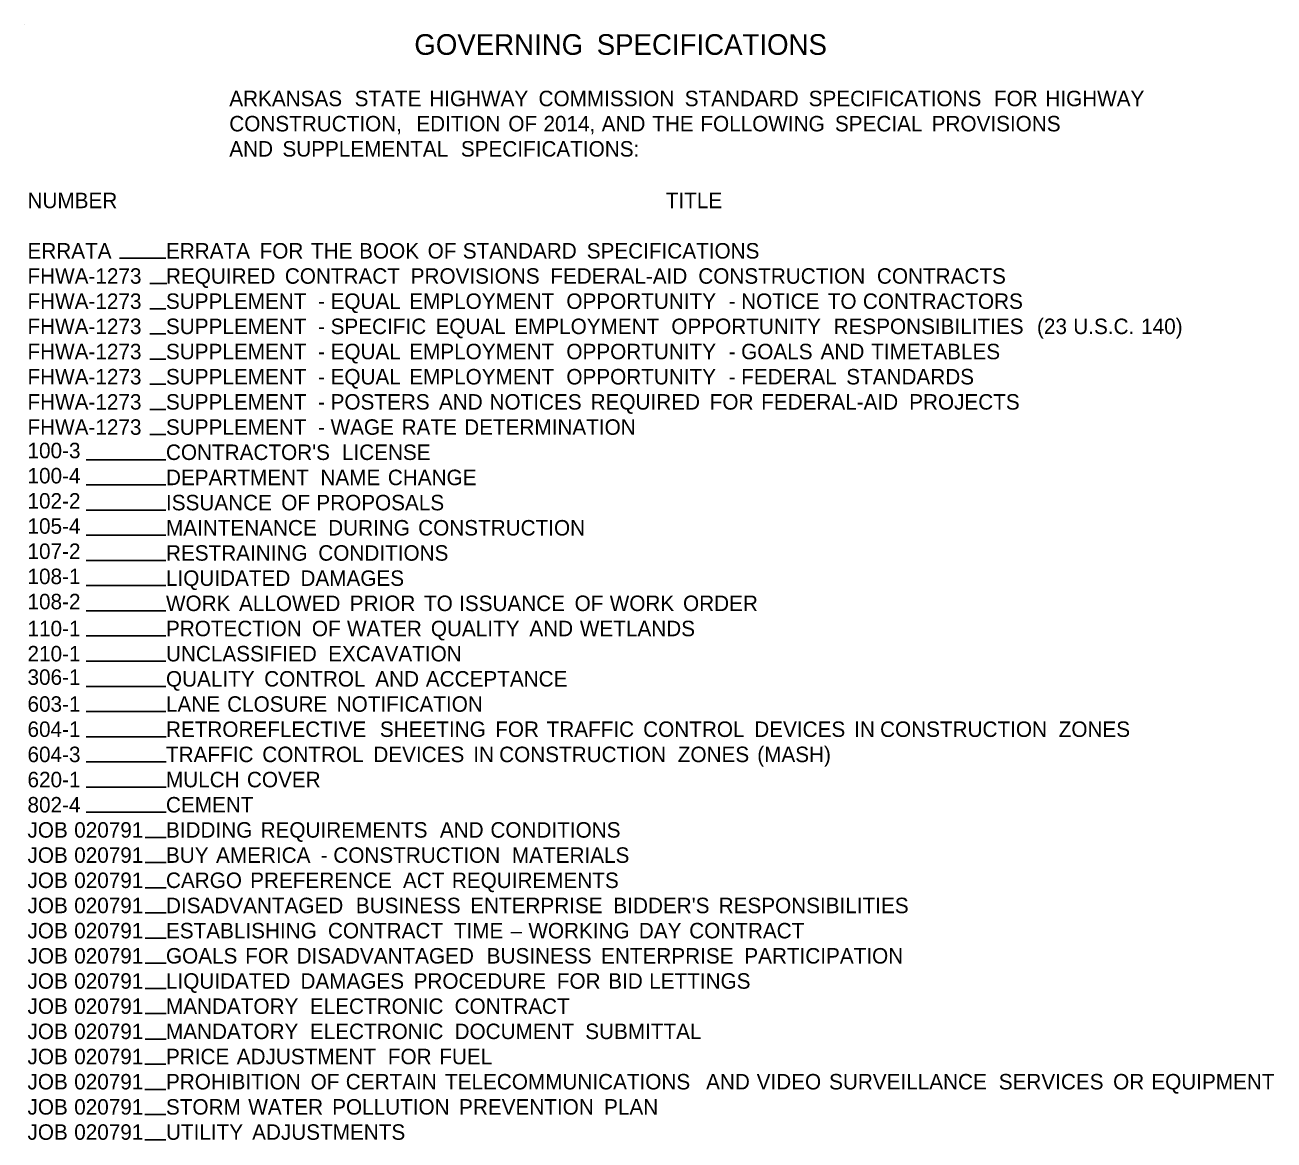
# Model space of a CAD drawing. Extents: x -1218 to 1646, y -1033 to 999.
# Drawn here: x -1218 to -250, y -181 to 682 of the extents above; entities that cross this region are included whole.
import ezdxf

# ---------------------------------------------------------------- set-up
doc = ezdxf.new("R2010")
doc.units = 0
doc.layers.add('Default', color=7, linetype='Continuous')

msp = doc.modelspace()

# ---------------------------------------------------------------- linework, layer by layer
at = {"layer": 'Default'}
for p, q in [((-1217.63, 682.26), (-1217.63, 682.26)), ((-1144.37, 501.55), (-1108.54, 501.55)), ((-1120.87, 482.05), (-1107.74, 482.05)), ((-1120.87, 462.55), (-1108.54, 462.55)), ((-1120.87, 443.05), (-1108.54, 443.05)), ((-1120.87, 423.55), (-1108.54, 423.55)), ((-1120.87, 404.05), (-1108.54, 404.05)), ((-1120.87, 384.55), (-1108.54, 384.55)), ((-1120.87, 365.05), (-1108.54, 365.05)), ((-1170.14, 345.55), (-1108.61, 345.55)), ((-1170.14, 326.05), (-1108.61, 326.05)), ((-1170.14, 306.55), (-1108.61, 306.55)), ((-1170.14, 287.05), (-1108.61, 287.05)), ((-1170.14, 267.55), (-1108.61, 267.55)), ((-1170.14, 248.05), (-1108.61, 248.05)), ((-1170.14, 228.55), (-1108.61, 228.55)), ((-1170.14, 209.05), (-1108.61, 209.05)), ((-1170.14, 189.55), (-1108.61, 189.55)), ((-1170.14, 170.05), (-1108.61, 170.05)), ((-1170.14, 150.55), (-1108.61, 150.55)), ((-1170.14, 131.05), (-1108.24, 131.05)), ((-1170.14, 111.55), (-1108.24, 111.55)), ((-1170.14, 92.05), (-1108.24, 92.05)), ((-1170.14, 72.55), (-1108.24, 72.55)), ((-1124.67, 53.05), (-1108.24, 53.05)), ((-1124.67, 33.55), (-1108.24, 33.55)), ((-1124.67, 14.05), (-1108.24, 14.05)), ((-1124.67, -5.45), (-1108.24, -5.45)), ((-1124.67, -24.95), (-1108.24, -24.95)), ((-1124.67, -44.45), (-1108.24, -44.45)), ((-1124.67, -63.95), (-1108.24, -63.95)), ((-1124.67, -83.45), (-1108.24, -83.45)), ((-1124.67, -103.14), (-1108.24, -103.14)), ((-1124.86, -122.64), (-1108.43, -122.64)), ((-1124.86, -142.14), (-1108.43, -142.14)), ((-1124.86, -161.51), (-1108.43, -161.51)), ((-1124.86, -181.27), (-1108.43, -181.27))]:
    msp.add_line(p, q, dxfattribs=at)

# ---------------------------------------------------------------- texts
for s, height, p in [('GOVERNING', 16, (-916.06, 659.14)), (' SPECIFICATIONS', 16, (-780.76, 659.14)), ('           ARKANSAS', 12, (-1108.43, 619.34)), (' STATE', 12, (-966.76, 619.34)), (' HIGHWAY', 12, (-908.96, 619.34)), (' COMMISSION', 12, (-824.32, 619.34)), (' STANDARD', 12, (-711.11, 619.34)), (' SPECIFICATIONS', 12, (-615.11, 619.34)), (' FOR', 12, (-471.58, 619.34)), (' HIGHWAY', 12, (-431.76, 619.34)), ('           CONSTRUCTION,', 12, (-1108.43, 599.84)), (' EDITION', 12, (-918.98, 599.84)), (' OF', 12, (-847.7, 599.84)), (' 2014,', 12, (-820.52, 599.84)), (' AND', 12, (-775.42, 599.84)), (' THE', 12, (-736.26, 599.84)), (' FOLLOWING', 12, (-698.96, 599.84)), (' SPECIAL', 12, (-594.75, 599.84)), (' PROVISIONS', 12, (-519.86, 599.84)), ('           AND', 12, (-1108.43, 580.34)), (' SUPPLEMENTAL', 12, (-1022.71, 580.34)), (' SPECIFICATIONS:', 12, (-884.47, 580.34)), ('NUMBER', 12, (-1215.68, 540.36)), ('TITLE', 12, (-721.31, 540.36)), ('ERRATA', 12, (-1215.68, 501.36)), ('ERRATA', 12, (-1108.43, 501.36)), (' FOR', 12, (-1040.38, 501.36)), (' THE', 12, (-1000.56, 501.36)), (' BOOK', 12, (-963.26, 501.36)), (' OF', 12, (-910.18, 501.36)), (' STANDARD', 12, (-883.01, 501.36)), (' SPECIFICATIONS', 12, (-787.01, 501.36)), ('FHWA-1273', 12, (-1215.68, 481.86)), ('REQUIRED', 12, (-1108.43, 481.86)), (' CONTRACT', 12, (-1020.82, 481.86)), (' PROVISIONS', 12, (-923.35, 481.86)), (' FEDERAL-AID', 12, (-815.21, 481.86)), (' CONSTRUCTION', 12, (-700.58, 481.86)), (' CONTRACTS', 12, (-562.22, 481.86)), ('FHWA-1273', 12, (-1215.68, 462.36)), ('SUPPLEMENT', 12, (-1108.43, 462.36)), (' EQUAL', 12, (-985.38, 462.36)), (' EMPLOYMENT', 12, (-924.47, 462.36)), (' OPPORTUNITY', 12, (-802.76, 462.36)), (' NOTICE', 12, (-667.4, 462.36)), (' TO', 12, (-600.3, 462.36)), (' CONTRACTORS', 12, (-573.11, 462.36)), (' -', 12, (-995.09, 462.36)), (' -', 12, (-677.12, 462.36)), ('FHWA-1273', 12, (-1215.68, 442.86)), ('SUPPLEMENT', 12, (-1108.43, 442.86)), (' SPECIFIC', 12, (-985.38, 442.86)), (' EQUAL', 12, (-904.06, 442.86)), (' EMPLOYMENT', 12, (-843.15, 442.86)), (' OPPORTUNITY', 12, (-721.44, 442.86)), (' RESPONSIBILITIES', 12, (-595.8, 442.86)), (' (23', 12, (-438.27, 442.86)), (' U.S.C.', 12, (-410.15, 442.86)), (' 140)', 12, (-357.59, 442.86)), (' -', 12, (-995.09, 442.86)), ('FHWA-1273', 12, (-1215.68, 423.36)), ('SUPPLEMENT', 12, (-1108.43, 423.36)), (' EQUAL', 12, (-985.38, 423.36)), (' EMPLOYMENT', 12, (-924.47, 423.36)), (' OPPORTUNITY', 12, (-802.76, 423.36)), (' GOALS', 12, (-667.4, 423.36)), (' AND', 12, (-605.85, 423.36)), (' TIMETABLES', 12, (-566.68, 423.36)), (' -', 12, (-995.09, 423.36)), (' -', 12, (-677.12, 423.36)), ('FHWA-1273', 12, (-1215.68, 403.86)), ('SUPPLEMENT', 12, (-1108.43, 403.86)), (' EQUAL', 12, (-985.38, 403.86)), (' EMPLOYMENT', 12, (-924.47, 403.86)), (' OPPORTUNITY', 12, (-802.76, 403.86)), (' STANDARDS', 12, (-586, 403.86)), (' -', 12, (-995.09, 403.86)), (' -', 12, (-677.12, 403.86)), (' FEDERAL', 12, (-667.4, 403.86)), ('FHWA-1273', 12, (-1215.68, 384.36)), ('SUPPLEMENT', 12, (-1108.43, 384.36)), (' -', 12, (-995.09, 384.36)), (' POSTERS', 12, (-985.38, 384.36)), (' AND', 12, (-901.46, 384.36)), (' NOTICES', 12, (-862.29, 384.36)), (' REQUIRED', 12, (-783.98, 384.36)), (' FOR', 12, (-691.72, 384.36)), (' FEDERAL-AID', 12, (-651.89, 384.36)), (' PROJECTS', 12, (-537.26, 384.36)), ('FHWA-1273', 12, (-1215.68, 364.86)), ('SUPPLEMENT', 12, (-1108.43, 364.86)), (' -', 12, (-995.09, 364.86)), (' WAGE', 12, (-985.38, 364.86)), (' RATE', 12, (-930.38, 364.86)), (' DETERMINATION', 12, (-881.9, 364.86)), ('100-3', 12, (-1215.68, 346.71)), ("CONTRACTOR'S", 12, (-1108.43, 345.36)), (' LICENSE', 12, (-976.61, 345.36)), ('100-4', 12, (-1215.68, 327.21)), ('DEPARTMENT', 12, (-1108.43, 325.86)), (' NAME', 12, (-993.24, 325.86)), (' CHANGE', 12, (-941.04, 325.86)), ('102-2', 12, (-1215.68, 307.71)), ('ISSUANCE', 12, (-1108.43, 306.36)), (' OF', 12, (-1023.6, 306.36)), (' PROPOSALS', 12, (-996.43, 306.36)), ('105-4', 12, (-1215.68, 288.21)), ('MAINTENANCE', 12, (-1108.43, 286.86)), (' DURING', 12, (-987.28, 286.86)), (' CONSTRUCTION', 12, (-917.54, 286.86)), ('107-2', 12, (-1215.68, 268.71)), ('RESTRAINING', 12, (-1108.43, 267.36)), (' CONDITIONS', 12, (-994.89, 267.36)), ('108-1', 12, (-1215.68, 249.21)), ('LIQUIDATED', 12, (-1108.43, 247.86)), (' DAMAGES', 12, (-1008.71, 247.86)), ('108-2', 12, (-1215.68, 229.71)), ('WORK', 12, (-1108.43, 228.36)), (' ALLOWED', 12, (-1056.31, 228.36)), (' PRIOR', 12, (-970.56, 228.36)), (' TO', 12, (-913.03, 228.36)), (' ISSUANCE', 12, (-885.84, 228.36)), (' OF', 12, (-796.35, 228.36)), (' WORK', 12, (-769.18, 228.36)), (' ORDER', 12, (-712.4, 228.36)), ('110-1', 12, (-1215.68, 208.86)), ('PROTECTION', 12, (-1108.43, 208.86)), (' OF', 12, (-999.87, 208.86)), (' WATER', 12, (-972.7, 208.86)), (' QUALITY', 12, (-907.72, 208.86)), (' AND', 12, (-831.45, 208.86)), (' WETLANDS', 12, (-792.29, 208.86)), ('210-1', 12, (-1215.68, 189.36)), ('UNCLASSIFIED', 12, (-1108.43, 189.36)), (' EXCAVATION', 12, (-987.27, 189.36)), ('306-1', 12, (-1215.68, 171.21)), ('QUALITY', 12, (-1108.43, 169.86)), (' CONTROL', 12, (-1036.82, 169.86)), (' AND', 12, (-950.78, 169.86)), (' ACCEPTANCE', 12, (-911.61, 169.86)), ('603-1', 12, (-1215.68, 150.36)), ('LANE', 12, (-1108.43, 150.36)), (' CLOSURE', 12, (-1065.53, 150.36)), (' NOTIFICATION', 12, (-980.7, 150.36)), ('604-1', 12, (-1215.68, 130.86)), ('RETROREFLECTIVE', 12, (-1108.43, 130.86)), (' SHEETING', 12, (-947.21, 130.86)), (' FOR', 12, (-857.89, 130.86)), (' TRAFFIC', 12, (-818.06, 130.86)), (' CONTROL', 12, (-743.28, 130.86)), (' DEVICES', 12, (-657.24, 130.86)), (' IN', 12, (-579.85, 130.86)), (' CONSTRUCTION', 12, (-559.8, 130.86)), (' ZONES', 12, (-421.44, 130.86)), ('604-3', 12, (-1215.68, 111.36)), ('TRAFFIC', 12, (-1108.43, 111.36)), (' CONTROL', 12, (-1038.31, 111.36)), (' DEVICES', 12, (-952.27, 111.36)), (' IN', 12, (-874.87, 111.36)), (' CONSTRUCTION', 12, (-854.82, 111.36)), (' ZONES', 12, (-716.47, 111.36)), (' (MASH)', 12, (-654.92, 111.36)), ('620-1', 12, (-1215.68, 91.86)), ('MULCH', 12, (-1108.43, 91.86)), (' COVER', 12, (-1050.17, 91.86)), ('802-4', 12, (-1215.68, 72.36)), ('CEMENT', 12, (-1108.43, 72.36)), ('JOB', 12, (-1215.68, 52.86)), (' 020791', 12, (-1183.96, 52.86)), ('BIDDING', 12, (-1108.43, 52.86)), (' REQUIREMENTS', 12, (-1039.61, 52.86)), (' AND', 12, (-900.75, 52.86)), (' CONDITIONS', 12, (-861.58, 52.86)), ('JOB', 12, (-1215.68, 33.36)), (' 020791', 12, (-1183.96, 33.36)), ('BUY', 12, (-1108.43, 33.36)), (' AMERICA', 12, (-1074.08, 33.36)), (' CONSTRUCTION', 12, (-983.28, 33.36)), (' MATERIALS', 12, (-844.93, 33.36)), (' -', 12, (-993, 33.36)), ('JOB', 12, (-1215.68, 13.86)), (' 020791', 12, (-1183.96, 13.86)), ('CARGO', 12, (-1108.43, 13.86)), (' PREFERENCE', 12, (-1047.69, 13.86)), (' ACT', 12, (-929.32, 13.86)), (' REQUIREMENTS', 12, (-891.46, 13.86)), ('JOB', 12, (-1215.68, -5.64)), (' 020791', 12, (-1183.96, -5.64)), ('DISADVANTAGED', 12, (-1108.43, -5.64)), (' BUSINESS', 12, (-965.83, -5.64)), (' ENTERPRISE', 12, (-877.25, -5.64)), (" BIDDER'S", 12, (-766.33, -5.64)), (' RESPONSIBILITIES', 12, (-684.81, -5.64)), ('JOB', 12, (-1215.68, -25.14)), (' 020791', 12, (-1183.96, -25.14)), ('ESTABLISHING', 12, (-1108.43, -25.14)), (' CONTRACT', 12, (-987.42, -25.14)), (' TIME', 12, (-889.94, -25.14)), (' WORKING', 12, (-832.19, -25.14)), (' DAY', 12, (-746.62, -25.14)), (' CONTRACT', 12, (-707.61, -25.14)), ('–', 12, (-841.48, -25.14)), ('JOB', 12, (-1215.68, -44.64)), (' 020791', 12, (-1183.96, -44.64)), ('GOALS', 12, (-1108.43, -44.64)), (' FOR', 12, (-1051.53, -44.64)), (' DISADVANTAGED', 12, (-1011.71, -44.64)), (' BUSINESS', 12, (-864.45, -44.64)), (' ENTERPRISE', 12, (-775.87, -44.64)), (' PARTICIPATION', 12, (-664.95, -44.64)), ('JOB', 12, (-1215.68, -64.14)), (' 020791', 12, (-1183.96, -64.14)), ('LIQUIDATED', 12, (-1108.43, -64.14)), (' DAMAGES', 12, (-1008.71, -64.14)), (' PROCEDURE', 12, (-921.07, -64.14)), (' FOR', 12, (-810.16, -64.14)), (' BID', 12, (-770.34, -64.14)), (' LETTINGS', 12, (-738.63, -64.14)), ('JOB', 12, (-1215.68, -83.64)), (' 020791', 12, (-1183.96, -83.64)), ('MANDATORY', 12, (-1108.43, -83.64)), (' ELECTRONIC', 12, (-1001.42, -83.64)), (' CONTRACT', 12, (-889.36, -83.64)), ('JOB', 12, (-1215.68, -103.14)), (' 020791', 12, (-1183.96, -103.14)), ('MANDATORY', 12, (-1108.43, -103.14)), (' ELECTRONIC', 12, (-1001.42, -103.14)), (' DOCUMENT', 12, (-889.36, -103.14)), (' SUBMITTAL', 12, (-788.16, -103.14)), ('JOB', 12, (-1215.68, -122.64)), (' 020791', 12, (-1183.96, -122.64)), ('PRICE', 12, (-1108.43, -122.64)), (' ADJUSTMENT', 12, (-1058.08, -122.64)), (' FOR', 12, (-941.04, -122.64)), (' FUEL', 12, (-901.21, -122.64)), ('JOB', 12, (-1215.68, -142.14)), (' 020791', 12, (-1183.96, -142.14)), ('PROHIBITION', 12, (-1108.43, -142.14)), (' OF', 12, (-1000.81, -142.14)), (' CERTAIN', 12, (-973.63, -142.14)), (' TELECOMMUNICATIONS', 12, (-896.75, -142.14)), (' AND', 12, (-694.54, -142.14)), (' VIDEO', 12, (-655.38, -142.14)), (' SURVEILLANCE', 12, (-599.29, -142.14)), (' SERVICES', 12, (-467.87, -142.14)), (' OR', 12, (-379.29, -142.14)), (' EQUIPMENT', 12, (-349.71, -142.14)), ('JOB', 12, (-1215.68, -161.64)), (' 020791', 12, (-1183.96, -161.64)), ('STORM', 12, (-1108.43, -161.64)), (' WATER', 12, (-1049.15, -161.64)), (' POLLUTION', 12, (-984.17, -161.64)), (' PREVENTION', 12, (-885.86, -161.64)), (' PLAN', 12, (-773.56, -161.64)), ('JOB', 12, (-1215.68, -181.14)), (' 020791', 12, (-1183.96, -181.14)), ('UTILITY', 12, (-1108.43, -181.14)), (' ADJUSTMENTS', 12, (-1046.15, -181.14))]:
    msp.add_text(s, height=height, dxfattribs=at).set_placement(p)

doc.saveas('drawing.dxf')
